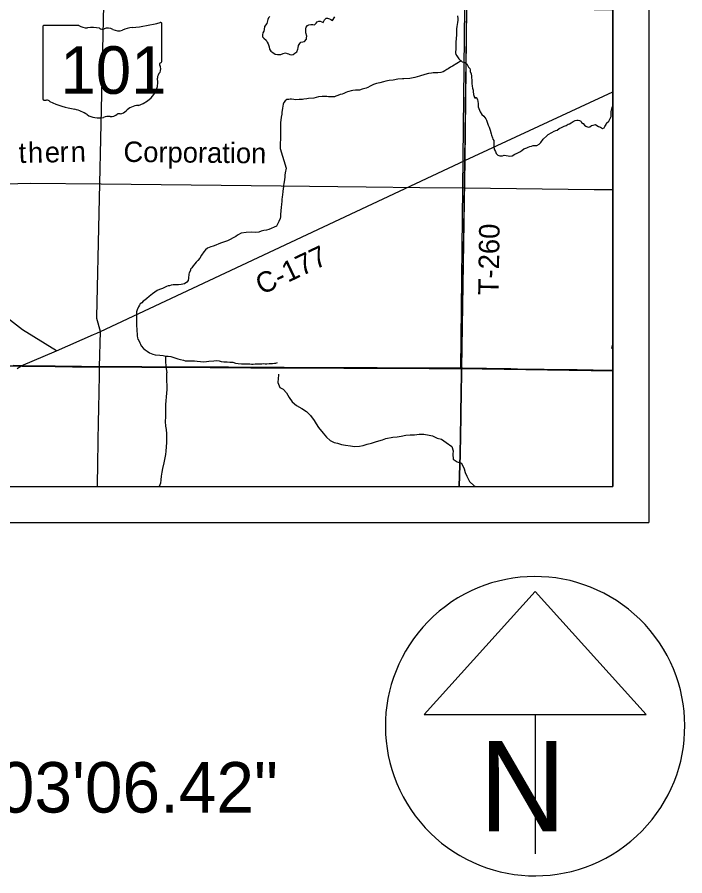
# Model space of a CAD drawing. Extents: x 0 to 34, y 0 to 22.
# Drawn here: x 7.25 to 9.099, y 13.02 to 15.401 of the extents above; entities that cross this region are included whole.
import ezdxf

# ---------------------------------------------------------------- set-up
doc = ezdxf.new("R2010")
doc.units = 0
for name, color, linetype in [('Default', 7, 'Continuous'), ('GM_X_County_Road', 7, 'Continuous'), ('GM_X_County_Road_Text', 7, 'Continuous'), ('GM_X_Minor_River', 7, 'Continuous'), ('GM_X_Rail_Line', 7, 'Continuous'), ('GM_X_Rail_Line_Text', 7, 'Continuous'), ('GM_X_State_Location', 7, 'Continuous'), ('GM_X_State_Route', 7, 'Continuous'), ('GM_X_State_Shield', 7, 'Continuous'), ('GM_X_Township', 7, 'Continuous'), ('GM_X_Township_Road', 7, 'Continuous'), ('GM_X_Township_Road_Text', 7, 'Continuous'), ('SH_Cut_Line', 7, 'Continuous'), ('SH_Data', 7, 'Continuous'), ('SH_Text', 7, 'Continuous')]:
    doc.layers.add(name, color=color, linetype=linetype)

msp = doc.modelspace()

# ---------------------------------------------------------------- linework, layer by layer
at = {"layer": 'Default'}
msp.add_lwpolyline([(8.9, 14.4202), (8.9, 15.4202), (8.489, 15.4271), (8.4778, 14.4266)], close=True, dxfattribs=at)
at = {"layer": 'GM_X_County_Road'}
for p, q in [((8.4898, 15.0036), (8.9, 15.1941)), ((7.4801, 14.5296), (8.4898, 15.0036))]:
    msp.add_line(p, q, dxfattribs=at)
for points in [[(6.4802, 14.433), (6.4888, 14.433), (6.5099, 14.4328), (6.5696, 14.4324), (6.6367, 14.4325), (6.7051, 14.4331), (6.8102, 14.4334), (6.858, 14.4333), (6.9003, 14.4334), (6.9463, 14.4337), (6.9904, 14.4339), (7.0389, 14.434), (7.0718, 14.4343), (7.111, 14.434), (7.1476, 14.4341), (7.203, 14.434), (7.2254, 14.4342), (7.239, 14.4341), (7.261, 14.4338)], [(7.261, 14.4338), (7.2632, 14.4337), (7.2843, 14.4331), (7.3552, 14.4325), (7.4031, 14.4318), (7.4279, 14.4315), (7.4775, 14.4313)], [(7.4718, 14.1), (7.4719, 14.1072), (7.473, 14.1594), (7.474, 14.2266), (7.4749, 14.2782), (7.4756, 14.3161), (7.4774, 14.4087), (7.4775, 14.4248), (7.4775, 14.4313)], [(7.4775, 14.4313), (7.5212, 14.4311), (7.5951, 14.4307), (7.6865, 14.4302), (7.7841, 14.4297), (7.8351, 14.4296), (7.8973, 14.4291), (7.9308, 14.4291), (7.9899, 14.4288), (8.0657, 14.4285), (8.1546, 14.4281), (8.2062, 14.4279), (8.2473, 14.4277), (8.3915, 14.4272), (8.4275, 14.427), (8.4813, 14.4267)], [(8.4813, 14.4267), (8.4835, 14.4267), (8.6171, 14.425), (8.6364, 14.4247), (8.7097, 14.4237), (8.7651, 14.4228), (8.8011, 14.4222), (8.8459, 14.4216), (8.9, 14.4209)]]:
    msp.add_lwpolyline(points, dxfattribs=at)
at = {"layer": 'GM_X_Minor_River'}
for points in [[(7.9496, 15.403), (7.9458, 15.3984), (7.9443, 15.3946), (7.9417, 15.3836), (7.9349, 15.3748), (7.9335, 15.3669), (7.9331, 15.3623), (7.9305, 15.357), (7.929, 15.3513), (7.9294, 15.3463), (7.9328, 15.3425), (7.9393, 15.3365), (7.9424, 15.3312), (7.9447, 15.3266), (7.9474, 15.3183), (7.9489, 15.3122), (7.9528, 15.3065), (7.9577, 15.3024), (7.9646, 15.2979), (7.971, 15.2971), (7.9798, 15.2976), (7.9866, 15.3002), (7.9934, 15.3014), (7.9976, 15.3003), (8.0014, 15.2992), (8.0052, 15.2969), (8.0101, 15.2962), (8.0147, 15.297), (8.0188, 15.3008), (8.0241, 15.3046), (8.0271, 15.3118), (8.0279, 15.3156), (8.0286, 15.3225), (8.0324, 15.3274), (8.0358, 15.3313), (8.0407, 15.3324), (8.0456, 15.3332)], [(8.0456, 15.3332), (8.0509, 15.3397), (8.0516, 15.3435), (8.0524, 15.3484), (8.0497, 15.3572), (8.0496, 15.3685), (8.0504, 15.3727), (8.0537, 15.3773), (8.0579, 15.3796), (8.0628, 15.3808), (8.0689, 15.3804), (8.0731, 15.3797), (8.078, 15.3839), (8.081, 15.3881), (8.0856, 15.3892), (8.0894, 15.3893), (8.0939, 15.3874), (8.0977, 15.3855), (8.1015, 15.3935), (8.1053, 15.3981), (8.1091, 15.3977), (8.1148, 15.3958), (8.1189, 15.3943), (8.1231, 15.3913), (8.1295, 15.4016)], [(8.47, 15.404), (8.4704, 15.3964), (8.4705, 15.3922), (8.4693, 15.3861)], [(8.4693, 15.3861), (8.4679, 15.3751), (8.4672, 15.3686), (8.4672, 15.361), (8.4668, 15.3572), (8.4665, 15.3496), (8.4658, 15.3432), (8.4658, 15.3386), (8.4654, 15.3341), (8.4651, 15.3268), (8.4651, 15.3158), (8.4648, 15.3101), (8.4644, 15.3059), (8.4637, 15.3018), (8.4645, 15.2972), (8.4675, 15.2934), (8.4733, 15.2851), (8.4828, 15.2768), (8.4896, 15.2749), (8.4954, 15.2715), (8.5, 15.2624), (8.5034, 15.2583), (8.5042, 15.2545), (8.5046, 15.2503), (8.5073, 15.2435), (8.5088, 15.237), (8.5089, 15.2226), (8.5097, 15.2169), (8.5105, 15.2093), (8.5109, 15.204), (8.5132, 15.1983), (8.5132, 15.1945), (8.5136, 15.1865), (8.5159, 15.1805), (8.5175, 15.1759), (8.5213, 15.179), (8.5247, 15.1729), (8.5267, 15.1615), (8.5267, 15.1524), (8.5283, 15.1471), (8.5325, 15.138), (8.5374, 15.1312), (8.5424, 15.1266), (8.5485, 15.1187), (8.5497, 15.1149), (8.5516, 15.1092), (8.5543, 15.1016), (8.5574, 15.0959), (8.5604, 15.0872), (8.5628, 15.0777), (8.5635, 15.0736), (8.5662, 15.0664), (8.5674, 15.0622), (8.5701, 15.0584), (8.5705, 15.0546), (8.5705, 15.0504), (8.5698, 15.0428), (8.5702, 15.039), (8.5717, 15.033), (8.5748, 15.0284), (8.5767, 15.0231), (8.5809, 15.0182), (8.587, 15.0159), (8.5938, 15.0163), (8.5991, 15.0183), (8.6098, 15.0164), (8.6139, 15.0157), (8.6211, 15.0165), (8.6283, 15.0207), (8.6344, 15.0241), (8.6423, 15.0276), (8.6476, 15.0314), (8.6533, 15.0356), (8.6613, 15.0383), (8.6651, 15.0399), (8.6696, 15.0422), (8.6742, 15.0429), (8.6791, 15.0449), (8.684, 15.0449), (8.6897, 15.0453), (8.6954, 15.0491), (8.7003, 15.0533), (8.7071, 15.0621), (8.7169, 15.0716), (8.7207, 15.0751), (8.7309, 15.0812), (8.7377, 15.0843), (8.7419, 15.0862), (8.7457, 15.0877), (8.7513, 15.0923), (8.7578, 15.0946), (8.765, 15.0988), (8.771, 15.1008), (8.776, 15.1042), (8.7797, 15.105), (8.7843, 15.108), (8.7903, 15.1111), (8.7956, 15.1142), (8.8002, 15.1153), (8.804, 15.1154), (8.8078, 15.1142)], [(8.4796, 15.2795), (8.4559, 15.2645), (8.4499, 15.2622), (8.4438, 15.2572), (8.4396, 15.2557), (8.4343, 15.2522), (8.4298, 15.2496), (8.423, 15.2476), (8.415, 15.2468), (8.4089, 15.2468), (8.4025, 15.2464), (8.3972, 15.2456), (8.3888, 15.2448), (8.3786, 15.2421), (8.3642, 15.2367), (8.3513, 15.2336), (8.3377, 15.2309), (8.321, 15.2297), (8.3168, 15.2296), (8.3039, 15.2284), (8.2914, 15.2261), (8.2807, 15.2253), (8.2709, 15.2234), (8.2644, 15.221), (8.2542, 15.2191), (8.2451, 15.2164), (8.2372, 15.2137), (8.2334, 15.2125), (8.2277, 15.2095), (8.2212, 15.206), (8.2163, 15.2037), (8.2057, 15.2014), (8.1978, 15.1987), (8.1871, 15.1983), (8.1792, 15.1978), (8.1746, 15.1967), (8.1682, 15.1947), (8.1644, 15.1936), (8.1598, 15.1921), (8.1549, 15.1894), (8.15, 15.1874), (8.1443, 15.1859), (8.1382, 15.1836), (8.1326, 15.1813), (8.1288, 15.1801), (8.1223, 15.1801), (8.1121, 15.18), (8.1071, 15.1804), (8.1033, 15.1808), (8.0992, 15.1804), (8.0942, 15.1807), (8.084, 15.1803), (8.0718, 15.1764), (8.0563, 15.1748), (8.0525, 15.1744), (8.0441, 15.1736), (8.0404, 15.1729), (8.0305, 15.1721), (8.0221, 15.172), (8.0157, 15.1727), (8.01, 15.1731), (8.0062, 15.1731), (8.0024, 15.1727), (7.9963, 15.1727), (7.9922, 15.1688), (7.9888, 15.1646), (7.9869, 15.1597), (7.9854, 15.1536), (7.9847, 15.1483), (7.9832, 15.1361), (7.9829, 15.1319), (7.9814, 15.1236), (7.9803, 15.1152), (7.9792, 15.1084), (7.9788, 15.1027), (7.9789, 15.0882), (7.9793, 15.0825), (7.979, 15.0776), (7.979, 15.0696), (7.9794, 15.0647), (7.9791, 15.0597), (7.9787, 15.054), (7.9783, 15.0491), (7.9784, 15.0453), (7.9784, 15.0362)], [(8.8078, 15.1142), (8.8116, 15.1127), (8.8128, 15.1089), (8.8173, 15.1059), (8.8211, 15.1014), (8.825, 15.0984), (8.8314, 15.0961), (8.8363, 15.0965), (8.8409, 15.1), (8.8454, 15.1011), (8.8515, 15.103), (8.8553, 15.1008), (8.8606, 15.0978), (8.8656, 15.0959), (8.8717, 15.0921), (8.8755, 15.094), (8.8773, 15.0979), (8.8811, 15.1028), (8.8822, 15.1066), (8.8887, 15.112), (8.892, 15.1177), (8.895, 15.1249), (8.895, 15.1393), (8.8961, 15.1431), (8.8976, 15.1504), (8.9, 15.1531)], [(7.9784, 15.0362), (7.9946, 14.9819), (7.992, 14.9694), (7.9909, 14.9626), (7.991, 14.9569), (7.9895, 14.9447), (7.9888, 14.9398), (7.9877, 14.9344), (7.9873, 14.9306), (7.9866, 14.9261), (7.9858, 14.9173), (7.9844, 14.9082), (7.984, 14.9029), (7.9833, 14.8957), (7.9826, 14.8892), (7.9822, 14.8835), (7.9808, 14.8721), (7.98, 14.8656), (7.9797, 14.8607), (7.9793, 14.8569), (7.9793, 14.852), (7.979, 14.847), (7.9782, 14.8428), (7.9745, 14.8341), (7.97, 14.8253), (7.9677, 14.8215), (7.9465, 14.8123), (7.9408, 14.8107), (7.9332, 14.8096), (7.9257, 14.8073), (7.9188, 14.8046), (7.9101, 14.8038), (7.8983, 14.8045), (7.8843, 14.8036), (7.8703, 14.8017), (7.8597, 14.7963), (7.8555, 14.7929), (7.8479, 14.7886), (7.84, 14.7844), (7.832, 14.7806), (7.8237, 14.7779), (7.8161, 14.7752), (7.8082, 14.7725), (7.7998, 14.7687), (7.7923, 14.766), (7.7858, 14.7637), (7.7817, 14.7621), (7.7767, 14.7602), (7.7714, 14.756), (7.7669, 14.7499), (7.7605, 14.7407), (7.7556, 14.7327), (7.7503, 14.7263), (7.7454, 14.7217), (7.7416, 14.7171), (7.7375, 14.7118), (7.7333, 14.706), (7.7303, 14.7019), (7.7296, 14.6981), (7.7262, 14.6923), (7.7255, 14.6882), (7.7244, 14.6768), (7.7237, 14.6711), (7.7195, 14.6657), (7.7135, 14.6611), (7.7089, 14.6607), (7.7036, 14.6596), (7.6964, 14.6591), (7.6884, 14.6587), (7.682, 14.6587), (7.6767, 14.6579), (7.6717, 14.6564), (7.6679, 14.6556), (7.6634, 14.654), (7.652, 14.6487), (7.6437, 14.6456), (7.6376, 14.6429), (7.6312, 14.6387), (7.6244, 14.6341), (7.6202, 14.6299), (7.6153, 14.6265), (7.6089, 14.6211), (7.6032, 14.6162), (7.5987, 14.6135), (7.5949, 14.6089), (7.5904, 14.6058), (7.5881, 14.602), (7.5859, 14.5975), (7.5825, 14.5895), (7.5806, 14.5841), (7.5803, 14.5781), (7.5799, 14.5724), (7.5803, 14.5651), (7.58, 14.5575), (7.58, 14.5515), (7.5804, 14.5458), (7.5809, 14.5351), (7.5813, 14.5302), (7.5821, 14.523), (7.5825, 14.5169), (7.5833, 14.512)], [(7.5833, 14.512), (7.584, 14.5082), (7.5867, 14.5044), (7.5894, 14.4979), (7.5909, 14.4942), (7.5936, 14.49), (7.5997, 14.4824), (7.6039, 14.479), (7.61, 14.4749), (7.6161, 14.4703), (7.6256, 14.4666), (7.6321, 14.4651), (7.6446, 14.4636), (7.6537, 14.4625), (7.6579, 14.4618), (7.6636, 14.4611), (7.6682, 14.4607), (7.6758, 14.4604), (7.6837, 14.4574), (7.6944, 14.454), (7.702, 14.4521), (7.71, 14.4499), (7.7149, 14.4484), (7.7195, 14.448), (7.7354, 14.4481), (7.7411, 14.4478), (7.7479, 14.4467), (7.7578, 14.4463), (7.7665, 14.4456), (7.7738, 14.4464), (7.781, 14.4472), (7.7946, 14.4484), (7.8015, 14.4492), (7.8094, 14.4477), (7.8148, 14.4462), (7.822, 14.4455), (7.8315, 14.4452), (7.8391, 14.4448), (7.8474, 14.4441), (7.8546, 14.4419), (7.8622, 14.4407), (7.8713, 14.44), (7.8797, 14.4397), (7.8888, 14.4397), (7.8941, 14.4394), (7.8991, 14.439), (7.9036, 14.439), (7.9089, 14.4395), (7.9188, 14.4395), (7.9275, 14.4399), (7.9317, 14.4403), (7.937, 14.44), (7.9416, 14.44), (7.9476, 14.4404), (7.9533, 14.4404), (7.9571, 14.4408), (7.9624, 14.4416), (7.9666, 14.442), (7.9708, 14.4432)], [(8.9, 14.495), (8.8997, 14.4943), (8.8982, 14.4905), (8.896, 14.4822)], [(7.6653, 14.4144), (7.6627, 14.4325), (7.662, 14.4355), (7.662, 14.4382), (7.6616, 14.4416), (7.6613, 14.4446), (7.6616, 14.4613)], [(7.6638, 14.4144), (7.6637, 14.4104), (7.6634, 14.4029), (7.6638, 14.3908), (7.6641, 14.3813), (7.6641, 14.3684), (7.6637, 14.3585), (7.6625, 14.3486), (7.6614, 14.3373), (7.6606, 14.3266), (7.6605, 14.2932), (7.6597, 14.2803), (7.6605, 14.2674), (7.662, 14.2579), (7.6631, 14.2461), (7.663, 14.2219), (7.6623, 14.2101), (7.6611, 14.1976), (7.6603, 14.1881), (7.6557, 14.1653), (7.6519, 14.1494), (7.6507, 14.1395), (7.6488, 14.1285), (7.6476, 14.1186), (7.6465, 14.1091), (7.6432, 14.1)], [(7.974, 14.4113), (7.9738, 14.4082), (7.9725, 14.3989), (7.9718, 14.3883), (7.977, 14.3742), (7.9869, 14.3693), (7.996, 14.3597), (8.0035, 14.3464), (8.0118, 14.3343), (8.0236, 14.3244), (8.0384, 14.3156), (8.0509, 14.308), (8.0626, 14.2962), (8.072, 14.2829), (8.0777, 14.2734), (8.0845, 14.2635), (8.097, 14.2479), (8.1068, 14.2361), (8.1167, 14.227), (8.1281, 14.2217), (8.1375, 14.2194), (8.1478, 14.2163), (8.1595, 14.214), (8.1728, 14.2125), (8.1845, 14.2102), (8.1982, 14.2113), (8.2081, 14.2135), (8.2191, 14.2166), (8.2316, 14.2199), (8.2449, 14.2241), (8.262, 14.2294), (8.2714, 14.2324), (8.2904, 14.2361), (8.3026, 14.2376), (8.3139, 14.2395), (8.3265, 14.2422), (8.3382, 14.2429), (8.3504, 14.2432), (8.3636, 14.2444), (8.3765, 14.2447), (8.3909, 14.242), (8.4004, 14.2397), (8.4129, 14.234), (8.4251, 14.2306), (8.4383, 14.2214), (8.4535, 14.2104), (8.4572, 14.1986), (8.4568, 14.1891), (8.4576, 14.1754), (8.4689, 14.1678), (8.4803, 14.1644), (8.4879, 14.1488), (8.4909, 14.1386), (8.4954, 14.1283), (8.503, 14.1139), (8.5158, 14.1017), (8.5193, 14.1)]]:
    msp.add_lwpolyline(points, dxfattribs=at)
at = {"layer": 'GM_X_Rail_Line'}
msp.add_lwpolyline([(7.2201, 14.9385), (7.2513, 14.9398), (7.2852, 14.9405), (7.4828, 14.9387), (7.9813, 14.9331), (8.2165, 14.9306), (8.3649, 14.9287), (8.4892, 14.9272), (8.8478, 14.9233), (8.9, 14.9228)], dxfattribs=at)
at = {"layer": 'GM_X_State_Route'}
msp.add_line((7.4708, 14.5691), (7.4898, 15.4344), dxfattribs=at)
for points in [[(7.47, 14.525), (7.4801, 14.5296), (7.4707, 14.5651), (7.4708, 14.5691)], [(7.261, 14.4338), (7.3588, 14.4754), (7.4608, 14.5208), (7.47, 14.525)], [(7.2494, 14.4269), (7.2551, 14.4304), (7.2596, 14.433), (7.261, 14.4338)]]:
    msp.add_lwpolyline(points, dxfattribs=at)
at = {"layer": 'GM_X_State_Shield'}
for p, q in [((7.4204, 15.3776), (7.3239, 15.3776)), ((7.6502, 15.2779), (7.6502, 15.3826)), ((7.3207, 15.3742), (7.3207, 15.174)), ((7.6502, 15.2779), (7.6502, 15.2779))]:
    msp.add_line(p, q, dxfattribs=at)
for centre, major_axis, start_param, end_param in [((7.3244, 15.3746), (0.00382, 0), 1.712693, 3.28349), ((7.4434, 15.4008), (0.037, 0), 4.042523, 4.731795), ((7.5328, 15.6504), (0.3495, 0), 4.814394, 5.042369), ((7.6466, 15.383), (0.00367, 0), 6.141152, 7.989035), ((7.4557, 15.2653), (0.133, 0), 1.404758, 1.657858), ((7.4859, 15.3756), (0.0107, 0), 3.836095, 5.185415), ((7.5015, 15.3525), (0.0222, 0), 0.950623, 2.079405), ((7.5302, 15.3842), (0.0267, 0), 4.081561, 5.145723), ((7.5774, 15.3165), (0.0703, 0), 1.699011, 2.107814), ((7.6494, 15.2702), (0.00568, 0), 1.883978, 3.671073), ((7.6133, 15.257), (0.0341, 0), 5.934695, 6.695948), ((7.6463, 15.2775), (0.00393, 0), 5.05454, 6.418171), ((7.6634, 15.2341), (0.0248, 0), 2.387724, 3.262537), ((7.5524, 15.2208), (0.0874, 0), 5.101752, 6.440018), ((7.3245, 15.1736), (0.00385, 0), 3.00124, 4.508301), ((7.325, 15.1941), (0.0294, 0), 4.665946, 4.897461), ((7.3311, 15.1625), (0.0106, 0), 0.519207, 1.627899), ((7.4649, 15.3423), (0.2524, 0), 4.195997, 4.488961), ((7.3896, 15.0841), (0.079, 0), 0.823519, 1.323587), ((7.5286, 15.1547), (0.0282, 0), 4.937069, 5.64225), ((7.5893, 15.1179), (0.0479, 0), 1.647645, 2.488434), ((7.475, 15.1615), (0.0501, 0), 4.026481, 4.996735), ((7.504, 15.0923), (0.0412, 0), 1.495662, 1.94098), ((7.5077, 15.1465), (0.0267, 0), 4.691044, 5.507374), ((7.5318, 15.1271), (0.00752, 0), 1.147584, 2.315152)]:
    msp.add_ellipse(centre, major_axis=major_axis, ratio=0.8, start_param=start_param, end_param=end_param, dxfattribs=at)
at = {"layer": 'GM_X_Township'}
msp.add_lwpolyline([(8.4947, 15.4259), (8.4895, 15.0042), (8.4811, 14.4273), (8.4273, 14.4275), (8.3913, 14.4277), (8.247, 14.4283), (8.206, 14.4285), (8.1544, 14.4287), (8.0655, 14.4291), (7.9897, 14.4293), (7.9306, 14.4296), (7.8971, 14.4297), (7.8349, 14.4301), (7.7839, 14.4303), (7.6863, 14.4307), (7.5949, 14.4312), (7.521, 14.4317), (7.4773, 14.4318), (7.4277, 14.432), (7.4028, 14.4324), (7.355, 14.433), (7.2841, 14.4337), (7.263, 14.4343), (7.2608, 14.4343), (7.2388, 14.4347)], dxfattribs=at)
at = {"layer": 'GM_X_Township_Road'}
msp.add_line((7.4775, 14.4313), (7.4801, 14.5296), dxfattribs=at)
for points in [[(8.9, 14.4215), (8.9, 20.4518), (8.556, 20.4544), (8.5437, 19.4556), (8.5436, 19.4447), (8.5388, 18.7451), (8.5216, 17.7888), (8.5215, 17.7806), (8.5214, 17.7731), (8.5094, 16.832), (8.5093, 16.83), (8.4947, 15.4259), (8.4895, 15.0042), (8.4811, 14.4273), (8.4833, 14.4273), (8.6169, 14.4256), (8.6362, 14.4253), (8.7095, 14.4242), (8.7648, 14.4233), (8.8009, 14.4228), (8.8456, 14.4221)], [(8.4746, 14.1), (8.9, 14.1), (8.9, 14.4215), (8.8456, 14.4221), (8.8009, 14.4228), (8.7648, 14.4233), (8.7095, 14.4242), (8.6362, 14.4253), (8.6169, 14.4256), (8.4833, 14.4273), (8.4811, 14.4273), (8.481, 14.4228), (8.4806, 14.4029), (8.48, 14.3693), (8.4784, 14.2929), (8.4767, 14.1891)]]:
    msp.add_lwpolyline(points, close=True, dxfattribs=at)
for points in [[(8.4813, 14.4267), (8.4898, 15.0036), (8.495, 15.4254)], [(7.3588, 14.4754), (7.2643, 14.534), (7.1516, 14.6207), (6.9923, 14.7488), (6.8515, 14.8606), (6.7328, 14.8957), (6.6733, 14.9117), (6.6038, 14.9221), (6.5837, 14.9281), (6.5345, 14.9785), (6.4297, 15.0819), (6.391, 15.1189), (6.3669, 15.1429), (6.3593, 15.1489)], [(2.3817, 14.1), (8.4746, 14.1), (8.4767, 14.1891), (8.4784, 14.2929), (8.48, 14.3693), (8.4806, 14.4029), (8.481, 14.4228), (8.4811, 14.4273), (8.4273, 14.4275), (8.3913, 14.4277), (8.247, 14.4283), (8.206, 14.4285), (8.1544, 14.4287), (8.0655, 14.4291), (7.9897, 14.4293), (7.9306, 14.4296), (7.8971, 14.4297), (7.8349, 14.4301), (7.7839, 14.4303), (7.6863, 14.4307), (7.5949, 14.4312), (7.521, 14.4317), (7.4773, 14.4318), (7.4277, 14.432), (7.4028, 14.4324), (7.355, 14.433), (7.2841, 14.4337), (7.263, 14.4343), (7.2608, 14.4343), (7.2388, 14.4347)], [(8.4749, 14.1), (8.477, 14.1885), (8.4786, 14.2923), (8.4803, 14.3688), (8.4808, 14.4023), (8.4812, 14.4222), (8.4813, 14.4267)]]:
    msp.add_lwpolyline(points, dxfattribs=at)
at = {"layer": 'SH_Cut_Line'}
for points in [[(7.2388, 14.4347), (7.2608, 14.4343), (7.263, 14.4343), (7.2841, 14.4337), (7.355, 14.433), (7.4028, 14.4324), (7.4277, 14.432), (7.4773, 14.4318), (7.521, 14.4317), (7.5949, 14.4312), (7.6863, 14.4307), (7.7839, 14.4303), (7.8349, 14.4301), (7.8971, 14.4297), (7.9306, 14.4296), (7.9897, 14.4293), (8.0655, 14.4291), (8.1544, 14.4287), (8.206, 14.4285), (8.247, 14.4283), (8.3913, 14.4277), (8.4273, 14.4275), (8.4811, 14.4273), (8.4833, 14.4273), (8.6169, 14.4256), (8.6362, 14.4253), (8.7095, 14.4242), (8.7648, 14.4233), (8.8009, 14.4228), (8.8456, 14.4221), (8.9, 14.4215), (8.9, 20.9)], [(2.1, 14.1), (8.9, 14.1), (8.9, 14.4215), (8.8456, 14.4221), (8.8009, 14.4228), (8.7648, 14.4233), (8.7095, 14.4242), (8.6362, 14.4253), (8.6169, 14.4256), (8.4833, 14.4273), (8.4811, 14.4273), (8.4273, 14.4275), (8.3913, 14.4277), (8.247, 14.4283), (8.206, 14.4285), (8.1544, 14.4287), (8.0655, 14.4291), (7.9897, 14.4293), (7.9306, 14.4296), (7.8971, 14.4297), (7.8349, 14.4301), (7.7839, 14.4303), (7.6863, 14.4307), (7.5949, 14.4312), (7.521, 14.4317), (7.4773, 14.4318), (7.4277, 14.432), (7.4028, 14.4324), (7.355, 14.433), (7.2841, 14.4337), (7.263, 14.4343), (7.2608, 14.4343), (7.2388, 14.4347)]]:
    msp.add_lwpolyline(points, dxfattribs=at)
at = {"layer": 'SH_Data'}
for p, q in [((9, 21), (9, 14)), ((8.9, 20.9), (8.9, 14.1)), ((2.1, 14.1), (8.9, 14.1)), ((2, 14), (9, 14)), ((8.6845, 13.809), (8.3769, 13.4678)), ((8.9921, 13.4678), (8.6845, 13.809)), ((8.3769, 13.4678), (8.9921, 13.4678)), ((8.6845, 13.4678), (8.6845, 13.081)), ((8.6845, 13.4353), (8.6845, 13.4353)), ((8.6845, 13.4353), (8.6845, 13.4353))]:
    msp.add_line(p, q, dxfattribs=at)
msp.add_arc((8.6845, 13.4353), 0.4148, 129.7798, 129.7633, dxfattribs=at)

# ---------------------------------------------------------------- texts
at = {"layer": 'GM_X_County_Road_Text'}
msp.add_text('C-177', height=0.05682, rotation=25.3333, dxfattribs=at).set_placement((7.9271, 14.63))
at = {"layer": 'GM_X_Rail_Line_Text'}
for s, height, rotation, p in [('t', 0.0566, 1.1951, (7.2543, 14.9963)), ('h', 0.0566, 1.1729, (7.2801, 14.9969)), ('r', 0.0566, 1.1697, (7.3676, 14.9987)), ('n', 0.0566, 1.1715, (7.3984, 14.9993)), ('Corporation', 0.056629, 359.3593, (7.5439, 14.9996)), ('e', 0.0566, 1.171, (7.3268, 14.9978))]:
    msp.add_text(s, height=height, rotation=rotation, dxfattribs=at).set_placement(p)
at = {"layer": 'GM_X_State_Location'}
for s in ['r', 's']:
    msp.add_text(s, height=0.000189, dxfattribs=at).set_placement((7.4817, 15.2608))
msp.add_text('101', height=0.000189, rotation=0, dxfattribs=at).set_placement((7.4149, 15.247))
at = {"layer": 'GM_X_State_Shield'}
msp.add_text('101', height=0.13184, dxfattribs=at).set_placement((7.3692, 15.1882))
at = {"layer": 'GM_X_Township_Road_Text'}
msp.add_text('T-260', height=0.05682, rotation=89.1579, dxfattribs=at).set_placement((8.5835, 14.6295))
at = {"layer": 'SH_Data'}
msp.add_text('N', height=0.25, dxfattribs=at).set_placement((8.5292, 13.1439))
at = {"layer": 'SH_Text'}
msp.add_text('LATITUDE:  N41°17\'45.81"   LONGITUDE:  W83°03\'06.42"', height=0.14, dxfattribs=at).set_placement((3.071, 13.1958))

doc.saveas('drawing.dxf')
